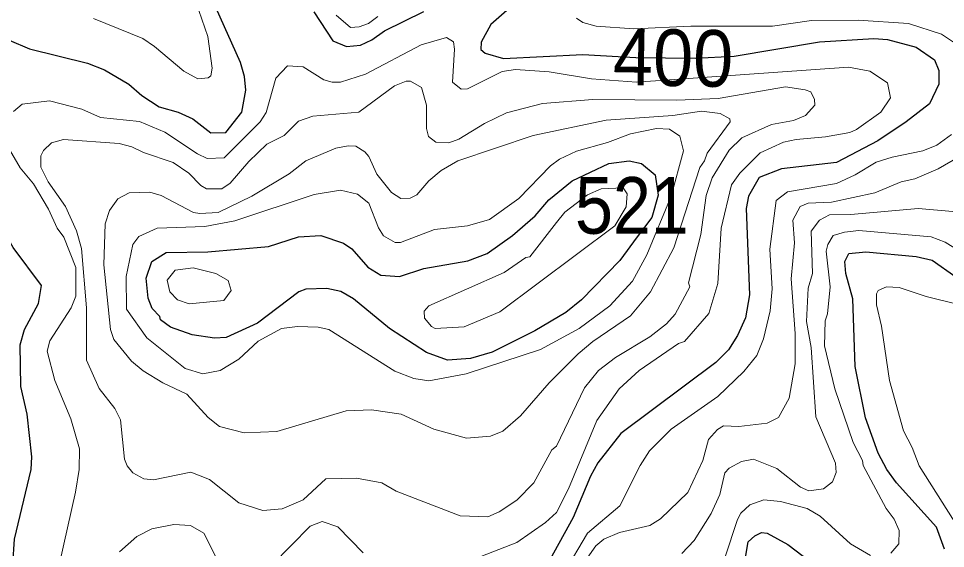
# Model space of a CAD drawing. Extents: x 673.3 to 698.5, y 6984.3 to 7012.3.
# Drawn here: x 693.321 to 694.629, y 6996.334 to 6997.082 of the extents above; entities that cross this region are included whole.
import ezdxf
from ezdxf.enums import TextEntityAlignment as Align

# ---------------------------------------------------------------- set-up
doc = ezdxf.new("R2010")
doc.units = 0
doc.header["$LTSCALE"] = 0.032
doc.layers.add('1', color=7, linetype='Continuous', lineweight=25)
doc.layers.add('2', color=7, linetype='Continuous', lineweight=13)
doc.layers.add('21', color=7, linetype='Continuous')
doc.layers.add('61', color=7, linetype='Continuous')

msp = doc.modelspace()

# ---------------------------------------------------------------- linework, layer by layer
at = {"layer": '1'}
for points in [[(693.3075, 6997.0519), (693.3361, 6997.0396), (693.4179, 6997.0194), (693.4417, 6997.01), (693.4762, 6996.9896), (693.4945, 6996.9739), (693.5192, 6996.9579), (693.546, 6996.9503), (693.5667, 6996.9409), (693.5922, 6996.9209), (693.613, 6996.9215), (693.6356, 6996.9501), (693.6413, 6996.981), (693.6397, 6997.0005), (693.6339, 6997.0204), (693.5991, 6997.098)], [(694.0173, 6997.1005), (693.9872, 6997.0738), (693.9737, 6997.0488), (693.973, 6997.0389), (693.9793, 6997.0336), (694.0053, 6997.0258), (694.1172, 6997.0315), (694.1919, 6997.0274), (694.2755, 6997.0265), (694.3305, 6997.0294), (694.4511, 6997.0495), (694.5276, 6997.0542), (694.5471, 6997.0528), (694.5876, 6997.042), (694.6135, 6997.0243), (694.6193, 6997.009), (694.6194, 6996.9895), (694.6061, 6996.962), (694.5733, 6996.9364), (694.5333, 6996.9097), (694.4749, 6996.8792), (694.3975, 6996.8703), (694.366, 6996.8578), (694.3508, 6996.8314), (694.3478, 6996.8141), (694.3523, 6996.692), (694.3467, 6996.6596), (694.3353, 6996.6344), (694.3227, 6996.6143), (694.3048, 6996.5964), (694.1705, 6996.4962), (694.1381, 6996.4549), (694.1279, 6996.436), (694.1035, 6996.3774), (694.0703, 6996.3179)], [(693.7374, 6997.0917), (693.7643, 6997.0511), (693.7834, 6997.043), (693.8034, 6997.0449), (693.8194, 6997.0525), (693.8371, 6997.065), (693.8926, 6997.0925)], [(693.3101, 6996.2753), (693.3147, 6996.3471), (693.3383, 6996.4451), (693.3392, 6996.4633), (693.3327, 6996.5233), (693.3237, 6996.5627), (693.323, 6996.6213), (693.3289, 6996.643), (693.3489, 6996.6798), (693.353, 6996.7055), (693.313, 6996.7589), (693.2973, 6996.7862), (693.2809, 6996.8239), (693.2648, 6996.8444), (693.2029, 6996.894), (693.1188, 6996.9424), (693.0668, 6996.9771), (693.0235, 6997.0004), (692.9917, 6997.0077)], [(694.6276, 6996.3326), (694.6161, 6996.3637), (694.5597, 6996.4266), (694.5461, 6996.4452), (694.534, 6996.4686), (694.516, 6996.5181), (694.5014, 6996.591), (694.498, 6996.6862), (694.4882, 6996.7223), (694.4867, 6996.7392), (694.4924, 6996.7504), (694.5163, 6996.7529), (694.5876, 6996.7464), (694.6103, 6996.7412), (694.6437, 6996.7175)], [(694.3462, 6996.3184), (694.3506, 6996.3431), (694.3599, 6996.3518), (694.3692, 6996.3562), (694.377, 6996.3554), (694.4066, 6996.3394), (694.4613, 6996.2973)]]:
    msp.add_lwpolyline(points, dxfattribs=at)
msp.add_lwpolyline([(693.6736, 6996.7603), (693.7155, 6996.774), (693.7472, 6996.7757), (693.7792, 6996.7653), (693.7908, 6996.7572), (693.8137, 6996.7312), (693.8321, 6996.72), (693.8584, 6996.718), (693.8924, 6996.7294), (693.9547, 6996.7401), (693.982, 6996.7507), (694.0178, 6996.7761), (694.0496, 6996.8038), (694.069, 6996.8262), (694.1022, 6996.8531), (694.1538, 6996.8774), (694.1825, 6996.8816), (694.2, 6996.8776), (694.2193, 6996.8614), (694.2236, 6996.8328), (694.2145, 6996.8011), (694.1937, 6996.7742), (694.1693, 6996.7405), (694.115, 6996.6852), (694.093, 6996.667), (694.0495, 6996.6411), (693.9893, 6996.611), (693.9586, 6996.6023), (693.9261, 6996.5999), (693.8964, 6996.6107), (693.8442, 6996.6445), (693.7934, 6996.6864), (693.7757, 6996.6968), (693.7558, 6996.7008), (693.7263, 6996.7), (693.7161, 6996.6962), (693.6579, 6996.6522), (693.6136, 6996.6317), (693.597, 6996.6309), (693.5655, 6996.6356), (693.5352, 6996.6465), (693.521, 6996.6567), (693.5198, 6996.6617), (693.5091, 6996.673), (693.5034, 6996.6875), (693.5005, 6996.7158), (693.5086, 6996.7391), (693.529, 6996.7521), (693.588, 6996.753)], close=True, dxfattribs=at)
at = {"layer": '2'}
for points in [[(693.5753, 6997.0937), (693.5876, 6997.0572), (693.5941, 6997.0125), (693.5922, 6997.0013), (693.5881, 6996.9987), (693.5738, 6996.9973), (693.5537, 6997.0082), (693.5124, 6997.0431), (693.4958, 6997.0541), (693.4266, 6997.0827)], [(693.8279, 6997.0854), (693.8144, 6997.0755), (693.8015, 6997.0706), (693.7893, 6997.0699), (693.769, 6997.0871)], [(694.6499, 6997.0424), (694.6231, 6997.0601), (694.5767, 6997.0756), (694.5056, 6997.0803), (694.4399, 6997.0795), (694.3846, 6997.0714), (694.2695, 6997.0717), (694.189, 6997.0681), (694.1358, 6997.0714), (694.1172, 6997.0769), (694.108, 6997.0829)], [(693.3135, 6996.9512), (693.3259, 6996.9615), (693.3644, 6996.9663), (693.4098, 6996.9542), (693.4362, 6996.9428), (693.4915, 6996.937), (693.5271, 6996.9217), (693.5732, 6996.8913), (693.5868, 6996.8849), (693.6109, 6996.8858), (693.6618, 6996.9365), (693.6699, 6996.9495), (693.6837, 6996.998), (693.7, 6997.0157), (693.7222, 6997.0144), (693.7515, 6996.9959), (693.7633, 6996.9924), (693.7752, 6996.9924), (693.8105, 6997.004), (693.8889, 6997.0453), (693.9247, 6997.0558), (693.9343, 6997.0496), (693.936, 6997.0391), (693.933, 6996.9925), (693.9454, 6996.9827), (693.9543, 6996.9829), (694.0032, 6997.0075), (694.022, 6997.0103), (694.0695, 6997.0071), (694.1293, 6996.9973), (694.1928, 6996.9924), (694.492, 6997.0136), (694.5219, 6997.008), (694.5469, 6996.9914), (694.5513, 6996.9705), (694.5377, 6996.95), (694.5035, 6996.9255), (694.4938, 6996.9213), (694.4595, 6996.9151), (694.418, 6996.9117), (694.4002, 6996.9076), (694.3675, 6996.8928), (694.3386, 6996.8639), (694.3271, 6996.8473), (694.3124, 6996.7861), (694.3075, 6996.708), (694.2947, 6996.6656), (694.2603, 6996.6262), (694.2521, 6996.6232), (694.1967, 6996.5852), (694.1684, 6996.5593), (694.1366, 6996.5146), (694.0968, 6996.418), (694.0798, 6996.3845), (694.0642, 6996.3704), (694.0239, 6996.3424), (693.8798, 6996.2862)], [(694.0902, 6996.2988), (694.1238, 6996.3553), (694.1692, 6996.3941), (694.198, 6996.4511), (694.211, 6996.4717), (694.2418, 6996.5025), (694.3075, 6996.5485), (694.3442, 6996.5836), (694.3628, 6996.6065), (694.372, 6996.6298), (694.3815, 6996.6697), (694.3841, 6996.7004), (694.3808, 6996.7565), (694.3898, 6996.8253), (694.406, 6996.8376), (694.4752, 6996.8495), (694.5016, 6996.8617), (694.531, 6996.8794), (694.5534, 6996.8865), (694.5967, 6996.8953), (694.6167, 6996.9035), (694.6376, 6996.9186)], [(693.3786, 6996.3123), (693.4011, 6996.4131), (693.406, 6996.4454), (693.4067, 6996.4743), (693.3944, 6996.5171), (693.3717, 6996.5712), (693.3612, 6996.6123), (693.3646, 6996.627), (693.3948, 6996.6737), (693.4015, 6996.6902), (693.4015, 6996.7308), (693.3843, 6996.7737), (693.375, 6996.7864), (693.3629, 6996.813), (693.3418, 6996.8489), (693.3231, 6996.8717), (693.3011, 6996.9086)], [(694.6696, 6996.8999), (694.6184, 6996.8701), (694.5858, 6996.8558), (694.5665, 6996.8515), (694.5293, 6996.8361), (694.4681, 6996.8231), (694.4351, 6996.8214), (694.4239, 6996.817), (694.4133, 6996.7974), (694.4158, 6996.7654), (694.411, 6996.7145), (694.4166, 6996.6376), (694.4166, 6996.5944), (694.4084, 6996.5461), (694.3931, 6996.5186), (694.3772, 6996.511), (694.3371, 6996.5063), (694.3157, 6996.507), (694.3073, 6996.5019), (694.2942, 6996.4878), (694.2863, 6996.4581), (694.2652, 6996.4128), (694.2268, 6996.3757), (694.2116, 6996.3663), (694.1687, 6996.3564), (694.1468, 6996.3469), (694.1355, 6996.3374), (694.1231, 6996.32)], [(694.4394, 6996.6178), (694.4329, 6996.6546), (694.4352, 6996.7015), (694.441, 6996.722), (694.4395, 6996.7822), (694.4509, 6996.7976), (694.4651, 6996.8052), (694.4954, 6996.8054), (694.5903, 6996.814), (694.6391, 6996.81)], [(694.5516, 6996.3269), (694.5631, 6996.3405), (694.5634, 6996.3593), (694.5566, 6996.3751), (694.5453, 6996.3903), (694.5128, 6996.4512), (694.5118, 6996.4581), (694.4986, 6996.4836), (694.4727, 6996.5591), (694.4582, 6996.6201), (694.459, 6996.6555), (694.4622, 6996.6651), (694.4662, 6996.7035), (694.4606, 6996.7536), (694.4626, 6996.7634), (694.4704, 6996.7757), (694.4864, 6996.7806), (694.5068, 6996.783), (694.6086, 6996.7742), (694.6286, 6996.7667), (694.671, 6996.7399)], [(694.6493, 6996.6781), (694.6017, 6996.6896), (694.5635, 6996.7024), (694.5454, 6996.7032), (694.5338, 6996.6982), (694.5313, 6996.6933), (694.5313, 6996.6781), (694.5386, 6996.6478), (694.5498, 6996.5709), (694.5694, 6996.5), (694.5818, 6996.4764), (694.5916, 6996.4503), (694.6565, 6996.348)], [(694.2569, 6996.3268), (694.2743, 6996.345), (694.2984, 6996.383), (694.3103, 6996.4099), (694.3175, 6996.4406), (694.3237, 6996.4473), (694.3411, 6996.4566), (694.3577, 6996.4597), (694.3908, 6996.4466), (694.4242, 6996.4202), (694.4359, 6996.4152), (694.4569, 6996.4181), (694.4692, 6996.4277), (694.4744, 6996.441), (694.4737, 6996.4543), (694.4461, 6996.5195), (694.4394, 6996.6178)], [(694.3176, 6996.3207), (694.3351, 6996.3749), (694.3402, 6996.3836), (694.3529, 6996.3952), (694.3727, 6996.4027), (694.396, 6996.4002), (694.4335, 6996.3902), (694.4522, 6996.3793), (694.4948, 6996.3401), (694.5232, 6996.3236)], [(693.6034, 6996.3135), (693.5819, 6996.3555), (693.5633, 6996.3661), (693.5397, 6996.3677), (693.5086, 6996.3615), (693.4874, 6996.3508), (693.4633, 6996.329)], [(693.8068, 6996.3276), (693.7712, 6996.3642), (693.749, 6996.3719), (693.7323, 6996.3651), (693.6787, 6996.3105)]]:
    msp.add_lwpolyline(points, dxfattribs=at)
for points in [[(693.4026, 6996.7825), (693.3871, 6996.8168), (693.3626, 6996.8519), (693.3523, 6996.8723), (693.3523, 6996.8883), (693.3559, 6996.896), (693.3669, 6996.9067), (693.384, 6996.9117), (693.4626, 6996.9061), (693.4806, 6996.9011), (693.4968, 6996.893), (693.539, 6996.8791), (693.5611, 6996.8641), (693.5779, 6996.8466), (693.5857, 6996.8417), (693.6074, 6996.8418), (693.6194, 6996.8499), (693.6457, 6996.8804), (693.671, 6996.9048), (693.6957, 6996.9173), (693.7155, 6996.9374), (693.7358, 6996.9443), (693.8008, 6996.9501), (693.851, 6996.9872), (693.8677, 6996.994), (693.8736, 6996.9939), (693.8895, 6996.985), (693.8962, 6996.9601), (693.8963, 6996.927), (693.8992, 6996.9156), (693.9096, 6996.9077), (693.9277, 6996.9069), (693.9418, 6996.9119), (693.9783, 6996.9343), (694.0094, 6996.9492), (694.0602, 6996.9623), (694.131, 6996.9679), (694.2496, 6996.9672), (694.3081, 6996.9696), (694.403, 6996.9858), (694.431, 6996.9819), (694.4389, 6996.9787), (694.4442, 6996.9679), (694.4445, 6996.9602), (694.4313, 6996.9455), (694.4146, 6996.9383), (694.3833, 6996.9329), (694.3415, 6996.914), (694.3235, 6996.8963), (694.2995, 6996.8575), (694.2911, 6996.8325), (694.2834, 6996.7771), (694.2663, 6996.709), (694.2679, 6996.7036), (694.2472, 6996.665), (694.2353, 6996.6511), (694.2117, 6996.6328), (694.163, 6996.6035), (694.1391, 6996.5853), (694.1192, 6996.5605), (694.0798, 6996.4785), (694.0731, 6996.473), (694.0479, 6996.4264), (694.0238, 6996.4018), (693.9991, 6996.3853), (693.983, 6996.3783), (693.9437, 6996.3801), (693.8536, 6996.4147), (693.8332, 6996.4263), (693.7975, 6996.433), (693.7542, 6996.4322), (693.7222, 6996.4024), (693.6928, 6996.3899), (693.6655, 6996.3874), (693.6313, 6996.398), (693.59, 6996.4312), (693.5637, 6996.4417), (693.511, 6996.4305), (693.4975, 6996.4321), (693.4821, 6996.4405), (693.474, 6996.4507), (693.4703, 6996.4599), (693.4644, 6996.5155), (693.4564, 6996.5314), (693.4344, 6996.5599), (693.4166, 6996.5997), (693.4165, 6996.6737), (693.4093, 6996.7575)], [(693.7832, 6996.5282), (693.8188, 6996.5298), (693.8607, 6996.5235), (693.9068, 6996.5022), (693.9529, 6996.4896), (693.9866, 6996.4922), (694.0039, 6996.4993), (694.0291, 6996.5211), (694.0694, 6996.5679), (694.1103, 6996.6088), (694.1312, 6996.6263), (694.1843, 6996.6624), (694.2126, 6996.6964), (694.2457, 6996.7586), (694.282, 6996.8722), (694.2886, 6996.8812), (694.2924, 6996.8924), (694.3249, 6996.9363), (694.3245, 6996.9409), (694.311, 6996.9484), (694.2845, 6996.9517), (694.2442, 6996.9452), (694.1498, 6996.9387), (694.0469, 6996.9174), (693.9408, 6996.8815), (693.917, 6996.8675), (693.8998, 6996.8533), (693.8828, 6996.8333), (693.8733, 6996.8285), (693.8602, 6996.8284), (693.8468, 6996.8365), (693.8262, 6996.8624), (693.815, 6996.8876), (693.8094, 6996.8942), (693.7968, 6996.9019), (693.7857, 6996.9028), (693.7683, 6996.8995), (693.7261, 6996.8816), (693.7024, 6996.8632), (693.6498, 6996.8313), (693.6025, 6996.8084), (693.5766, 6996.8068), (693.5677, 6996.8085), (693.5219, 6996.8322), (693.5059, 6996.8369), (693.4769, 6996.836), (693.4609, 6996.8276), (693.449, 6996.8114), (693.4427, 6996.7923), (693.4409, 6996.7345), (693.4505, 6996.6432), (693.4553, 6996.629), (693.48, 6996.5983), (693.4964, 6996.5846), (693.5243, 6996.5679), (693.5582, 6996.5518), (693.5881, 6996.5187), (693.6044, 6996.506), (693.6391, 6996.4973), (693.685, 6996.4989)], [(694.2593, 6996.8953), (694.254, 6996.916), (694.2394, 6996.9262), (694.2209, 6996.9272), (694.1844, 6996.9197), (694.1518, 6996.9074), (694.1081, 6996.895), (694.0839, 6996.8837), (694.0713, 6996.8743), (694.0267, 6996.828), (693.9853, 6996.7983), (693.9543, 6996.7897), (693.9075, 6996.7845), (693.8596, 6996.7661), (693.852, 6996.7661), (693.8358, 6996.7752), (693.8287, 6996.7868), (693.8148, 6996.8214), (693.7992, 6996.8344), (693.7752, 6996.84), (693.7377, 6996.8336), (693.6257, 6996.7967), (693.5833, 6996.7886), (693.5162, 6996.7864), (693.4905, 6996.7747), (693.4817, 6996.7633), (693.4726, 6996.7178), (693.4728, 6996.6718), (693.5017, 6996.6313), (693.5557, 6996.5882), (693.5808, 6996.5804), (693.6053, 6996.5852), (693.6315, 6996.6013), (693.6588, 6996.6264), (693.6918, 6996.6446), (693.7142, 6996.6472), (693.7436, 6996.6463), (693.7587, 6996.6429), (693.8517, 6996.5843), (693.8785, 6996.574), (693.8997, 6996.5706), (693.9524, 6996.5803), (694.0572, 6996.6148), (694.1118, 6996.6445), (694.1553, 6996.6766), (694.187, 6996.7116), (694.2076, 6996.7485), (694.2416, 6996.8314)], [(694.1623, 6996.7894), (694.1782, 6996.8162), (694.1796, 6996.835), (694.174, 6996.8431), (694.143, 6996.8417), (694.1234, 6996.8335), (694.0917, 6996.8091), (694.08, 6996.7945), (694.0422, 6996.7459), (694.0364, 6996.7448), (694.0059, 6996.7235), (693.8996, 6996.6764), (693.8931, 6996.669), (693.8934, 6996.659), (693.9034, 6996.6473), (693.9088, 6996.6446), (693.9494, 6996.6471), (693.9999, 6996.6679)], [(693.5448, 6996.6852), (693.5341, 6996.6965), (693.5306, 6996.713), (693.5417, 6996.727), (693.567, 6996.7301), (693.599, 6996.722), (693.6167, 6996.7124), (693.6208, 6996.6983), (693.6105, 6996.6841), (693.5613, 6996.6796)]]:
    msp.add_lwpolyline(points, close=True, dxfattribs=at)

# ---------------------------------------------------------------- texts
at = {"layer": '21', "width": 0.9}
msp.add_text('521', height=0.08, dxfattribs=at).set_placement((694.106, 6996.7784))
at = {"layer": '61', "width": 0.95}
msp.add_text('400', height=0.08, rotation=358.982, dxfattribs=at).set_placement((694.2438, 6996.9871), align=Align.CENTER)

doc.saveas('drawing.dxf')
